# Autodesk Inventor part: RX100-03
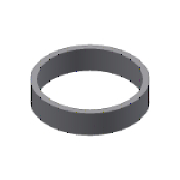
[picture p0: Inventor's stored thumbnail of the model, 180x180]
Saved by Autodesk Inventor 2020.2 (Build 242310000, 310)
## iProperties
Manager: www.cadconsulting.pl
Company: Fabian Stasiak CAD Consulting
Created: 2014-07
Part Number: RX100-03
Material: Ogólny
Document SubType Name: Modeling
Standard: DIN EN 1661
Designer: F.Stasiak
Manufacturer: KeroX
Standards Organization: DIN
Language: pl-PL
Size Designation: 60
Categories: <MemberInstance><Categories><Category DisplayName="Rury cienko- i grubościenne" InternalName="4347fa0f-2144-441d-94cd-e3e15c92b736" Mnemonic="TUBEANDPIPE"><Cate
Density: 1 g/cm^3
Appearance: Domyślna
Catalog Web Link: www.expertbooks.pl
IsCustomPart: 0
Author: F.Stasiak
Subject: Zbiór ćwiczeń. Autodesk Inventor 2020. Kurs Professional
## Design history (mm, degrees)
sketch "Szkic1"
  geometry: C1 r 30 at (0, 0); C2 r 32.5 at (0, 0); 1 further point
  constraints: 2 centre point, 2 coincident
  dimensions: "ID" = 60 diameter of C1; "OD" = 65 diameter of C2
extrude "Wyciągnięcie proste1" new body sketch "Szkic1" taper "d3" = 0 deg; distance "L" = 10
node "Punkt konstrukcyjny1"
node "Punkt konstrukcyjny2"
node "Oś konstrukcyjna1"
node "Oś konstrukcyjna2"
node "Bryła1"
